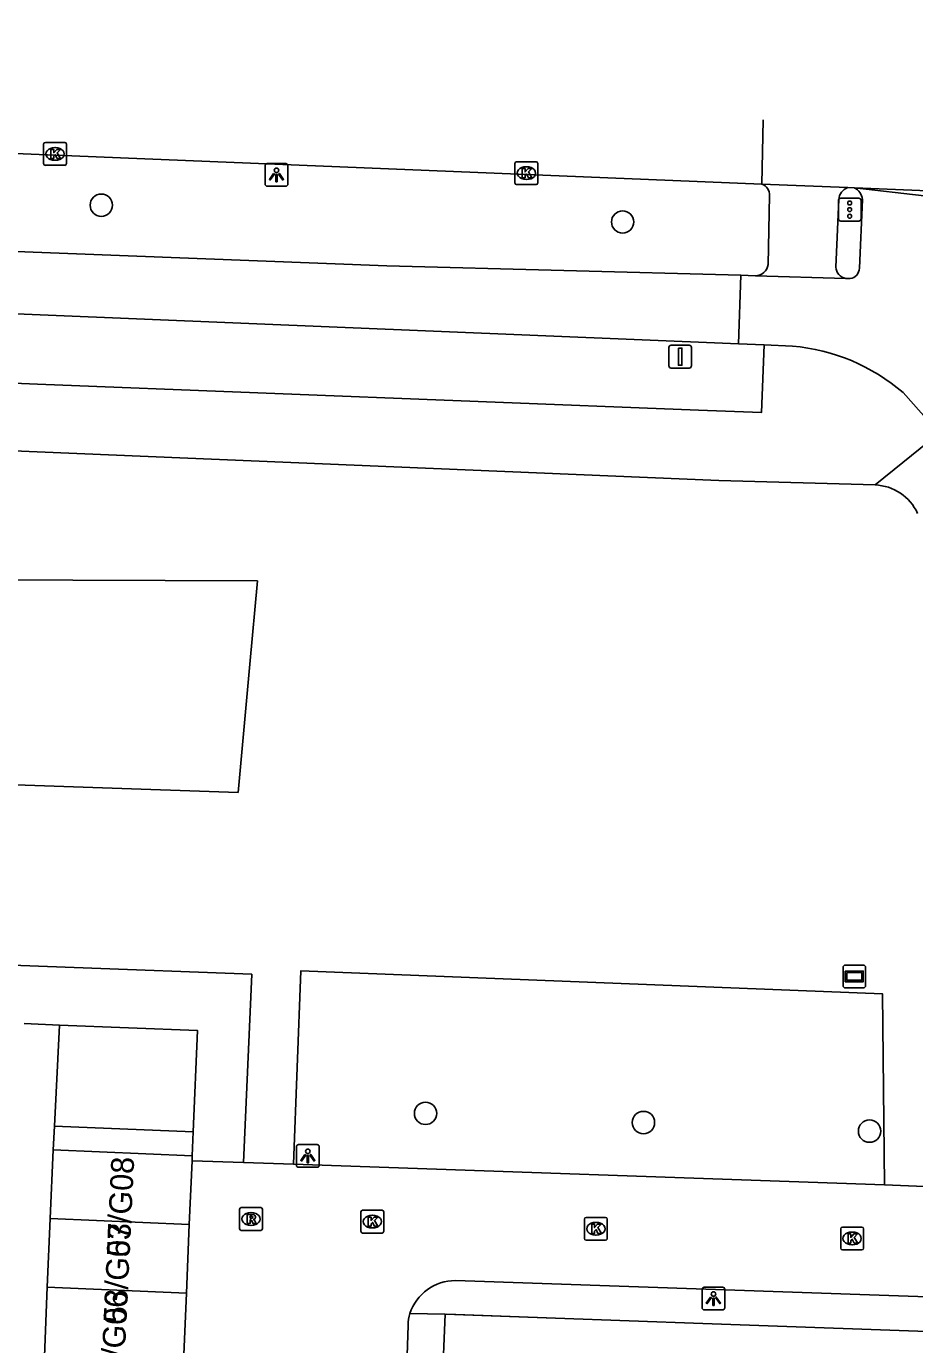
# Model space of a CAD drawing. Extents: x 161355 to 162026, y 386504 to 387459.
# Drawn here: x 161707.5 to 161746.4, y 387393.1 to 387450.8 of the extents above; entities that cross this region are included whole.
import ezdxf

# ---------------------------------------------------------------- set-up
doc = ezdxf.new("R2010")
doc.units = 0
for name, color, linetype in [('IMGEO_Boom', 7, 'Continuous'), ('IMGEO_Fietspad_gesloten', 7, 'Continuous'), ('IMGEO_Fietspad_open', 7, 'Continuous'), ('IMGEO_Groenvoorziening', 7, 'Continuous'), ('IMGEO_Kolk', 7, 'Continuous'), ('IMGEO_Lichtpunt', 7, 'Continuous'), ('IMGEO_Muur', 7, 'Continuous'), ('IMGEO_Pand', 7, 'Continuous'), ('IMGEO_Pand_nummerreeks', 7, 'Continuous'), ('IMGEO_Rijbaan_lokaal_gesloten', 7, 'Continuous'), ('IMGEO_Rijbaan_lokaal_open', 7, 'Continuous'), ('IMGEO_Rioolput', 7, 'Continuous'), ('IMGEO_Verkeersbordpaal', 7, 'Continuous'), ('IMGEO_Verkeersregelinstallatiepaal', 7, 'Continuous'), ('IMGEO_Verklikker', 7, 'Continuous'), ('IMGEO_Voetpad_open', 7, 'Continuous')]:
    doc.layers.add(name, color=color, linetype=linetype)

msp = doc.modelspace()

# ---------------------------------------------------------------- linework, layer by layer
at = {"layer": 'IMGEO_Boom'}
for centre in [(161710.741, 387443.016), (161733.577, 387442.282), (161724.944, 387403.261), (161734.491, 387402.86), (161744.394, 387402.483)]:
    msp.add_circle(centre, 0.489, dxfattribs=at)
at = {"layer": 'IMGEO_Fietspad_gesloten'}
for points in [[(161612.89, 387444.91), (161652.822, 387443.267), (161706.244, 387441.015), (161723.243, 387440.365), (161738.753, 387439.947)], [(161610.883, 387442.256), (161612.683, 387442.214), (161614.558, 387442.129), (161644.429, 387440.874), (161676.294, 387439.535), (161679.83, 387439.386), (161708.067, 387438.213), (161738.649, 387436.943)], [(161738.753, 387439.947), (161738.649, 387436.943)]]:
    msp.add_lwpolyline(points, dxfattribs=at)
at = {"layer": 'IMGEO_Fietspad_open'}
for points in [[(161744.081, 387443.272), (161743.952, 387440.258)], [(161739.398, 387439.93), (161738.753, 387439.947)], [(161743.359, 387439.812), (161739.398, 387439.93)], [(161743.542, 387439.801), (161743.359, 387439.812)], [(161738.649, 387436.943), (161739.77, 387436.897)], [(161739.77, 387436.897), (161741.023, 387436.845)], [(161745.866, 387434.812), (161747.439, 387433.041)]]:
    msp.add_lwpolyline(points, dxfattribs=at)
for centre, radius, start, end in [((161743.477, 387443.221), 0.606, 4.7809, 64.80063), ((161743.474, 387440.274), 0.478, 278.16907, 358.03686), ((161740.308, 387428.357), 8.518, 49.27042, 85.18609)]:
    msp.add_arc(centre, radius, start, end, dxfattribs=at)
at = {"layer": 'IMGEO_Groenvoorziening'}
for points in [[(161697.286, 387423.717), (161697.204, 387417.981), (161716.731, 387417.308), (161717.248, 387422.919), (161717.584, 387426.568), (161697.328, 387426.639), (161697.286, 387423.717)], [(161745.049, 387400.136), (161744.963, 387408.488), (161719.485, 387409.508), (161719.159, 387401.034)]]:
    msp.add_lwpolyline(points, dxfattribs=at)
at = {"layer": 'IMGEO_Kolk'}
for p, q in [((161708.216, 387444.836), (161708.216, 387445.688)), ((161708.291, 387445.762), (161709.143, 387445.762)), ((161708.704, 387445.542), (161708.729, 387445.542)), ((161709.217, 387445.688), (161709.217, 387444.836)), ((161708.727, 387444.982), (161708.702, 387444.982)), ((161728.861, 387443.995), (161728.861, 387444.847)), ((161728.936, 387444.921), (161729.788, 387444.921)), ((161729.862, 387444.847), (161729.862, 387443.995)), ((161709.143, 387444.762), (161708.291, 387444.762)), ((161729.349, 387444.701), (161729.374, 387444.701)), ((161729.788, 387443.921), (161728.936, 387443.921)), ((161729.372, 387444.141), (161729.347, 387444.141)), ((161722.115, 387398.098), (161722.115, 387398.95)), ((161722.19, 387399.024), (161723.042, 387399.024)), ((161722.603, 387398.804), (161722.628, 387398.804)), ((161723.116, 387398.95), (161723.116, 387398.098)), ((161731.905, 387397.784), (161731.905, 387398.636)), ((161731.98, 387398.71), (161732.832, 387398.71)), ((161732.906, 387398.636), (161732.906, 387397.784)), ((161722.626, 387398.244), (161722.601, 387398.244)), ((161732.393, 387398.49), (161732.418, 387398.49)), ((161743.129, 387397.36), (161743.129, 387398.212)), ((161743.204, 387398.286), (161744.056, 387398.286)), ((161743.617, 387398.066), (161743.642, 387398.066)), ((161744.13, 387398.212), (161744.13, 387397.36)), ((161723.042, 387398.024), (161722.19, 387398.024)), ((161732.832, 387397.71), (161731.98, 387397.71)), ((161732.416, 387397.93), (161732.391, 387397.93)), ((161743.64, 387397.506), (161743.615, 387397.506)), ((161744.056, 387397.286), (161743.204, 387397.286))]:
    msp.add_line(p, q, dxfattribs=at)
for points in [[(161708.216, 387444.836), (161708.216, 387445.688)], [(161708.291, 387445.762), (161709.143, 387445.762)], [(161708.537, 387445.462), (161708.66, 387445.462), (161708.66, 387445.311), (161708.79, 387445.462), (161708.954, 387445.462), (161708.808, 387445.311), (161708.961, 387445.062), (161708.809, 387445.062), (161708.724, 387445.226), (161708.66, 387445.159), (161708.66, 387445.062), (161708.537, 387445.062), (161708.537, 387445.462)], [(161709.217, 387445.688), (161709.217, 387444.836)], [(161728.861, 387443.995), (161728.861, 387444.847)], [(161728.936, 387444.921), (161729.788, 387444.921)], [(161729.862, 387444.847), (161729.862, 387443.995)], [(161709.143, 387444.762), (161708.291, 387444.762)], [(161729.182, 387444.621), (161729.305, 387444.621), (161729.305, 387444.47), (161729.435, 387444.621), (161729.599, 387444.621), (161729.453, 387444.47), (161729.606, 387444.221), (161729.454, 387444.221), (161729.369, 387444.385), (161729.305, 387444.318), (161729.305, 387444.221), (161729.182, 387444.221), (161729.182, 387444.621)], [(161729.788, 387443.921), (161728.936, 387443.921)], [(161722.115, 387398.098), (161722.115, 387398.95)], [(161722.19, 387399.024), (161723.042, 387399.024)], [(161722.436, 387398.724), (161722.559, 387398.724), (161722.559, 387398.573), (161722.689, 387398.724), (161722.853, 387398.724), (161722.707, 387398.573), (161722.86, 387398.324), (161722.708, 387398.324), (161722.623, 387398.488), (161722.559, 387398.421), (161722.559, 387398.324), (161722.436, 387398.324), (161722.436, 387398.724)], [(161723.116, 387398.95), (161723.116, 387398.098)], [(161731.905, 387397.784), (161731.905, 387398.636)], [(161731.98, 387398.71), (161732.832, 387398.71)], [(161732.906, 387398.636), (161732.906, 387397.784)], [(161732.226, 387398.41), (161732.349, 387398.41), (161732.349, 387398.259), (161732.479, 387398.41), (161732.643, 387398.41), (161732.497, 387398.259), (161732.65, 387398.01), (161732.498, 387398.01), (161732.413, 387398.174), (161732.349, 387398.107), (161732.349, 387398.01), (161732.226, 387398.01), (161732.226, 387398.41)], [(161743.129, 387397.36), (161743.129, 387398.212)], [(161743.204, 387398.286), (161744.056, 387398.286)], [(161744.13, 387398.212), (161744.13, 387397.36)], [(161723.042, 387398.024), (161722.19, 387398.024)], [(161732.832, 387397.71), (161731.98, 387397.71)], [(161743.45, 387397.986), (161743.573, 387397.986), (161743.573, 387397.835), (161743.703, 387397.986), (161743.867, 387397.986), (161743.721, 387397.835), (161743.874, 387397.586), (161743.722, 387397.586), (161743.637, 387397.75), (161743.573, 387397.683), (161743.573, 387397.586), (161743.45, 387397.586), (161743.45, 387397.986)], [(161744.056, 387397.286), (161743.204, 387397.286)]]:
    msp.add_lwpolyline(points, dxfattribs=at)
for centre, start, end in [((161708.293, 387445.686), 91.55205, 178.44795), ((161708.293, 387445.686), 91.55205, 178.44795), ((161709.141, 387445.686), 1.55205, 88.44795), ((161709.141, 387445.686), 1.55205, 88.44795), ((161708.293, 387444.838), 181.55205, 268.44795), ((161708.293, 387444.838), 181.55205, 268.44795), ((161709.141, 387444.838), 271.55205, 358.44795), ((161709.141, 387444.838), 271.55205, 358.44795), ((161728.938, 387444.845), 91.55205, 178.44795), ((161728.938, 387444.845), 91.55205, 178.44795), ((161729.786, 387444.845), 1.55205, 88.44795), ((161729.786, 387444.845), 1.55205, 88.44795), ((161728.938, 387443.997), 181.55205, 268.44795), ((161728.938, 387443.997), 181.55205, 268.44795), ((161729.786, 387443.997), 271.55205, 358.44795), ((161729.786, 387443.997), 271.55205, 358.44795), ((161722.192, 387398.948), 91.55205, 178.44795), ((161722.192, 387398.948), 91.55205, 178.44795), ((161723.04, 387398.948), 1.55205, 88.44795), ((161723.04, 387398.948), 1.55205, 88.44795), ((161731.982, 387398.634), 91.55205, 178.44795), ((161731.982, 387398.634), 91.55205, 178.44795), ((161732.83, 387398.634), 1.55205, 88.44795), ((161732.83, 387398.634), 1.55205, 88.44795), ((161722.192, 387398.1), 181.55205, 268.44795), ((161722.192, 387398.1), 181.55205, 268.44795), ((161723.04, 387398.1), 271.55205, 358.44795), ((161723.04, 387398.1), 271.55205, 358.44795), ((161743.206, 387398.21), 91.55205, 178.44795), ((161743.206, 387398.21), 91.55205, 178.44795), ((161744.054, 387398.21), 1.55205, 88.44795), ((161744.054, 387398.21), 1.55205, 88.44795), ((161731.982, 387397.786), 181.55205, 268.44795), ((161731.982, 387397.786), 181.55205, 268.44795), ((161732.83, 387397.786), 271.55205, 358.44795), ((161732.83, 387397.786), 271.55205, 358.44795), ((161743.206, 387397.362), 181.55205, 268.44795), ((161743.206, 387397.362), 181.55205, 268.44795), ((161744.054, 387397.362), 271.55205, 358.44795), ((161744.054, 387397.362), 271.55205, 358.44795)]:
    msp.add_arc(centre, 0.0765, start, end, dxfattribs=at)
for centre, major_axis, ratio, start_param, end_param in [((161708.703, 387445.262), (-0.387, 0.002), 0.722429, 4.712389, 7.853982), ((161708.728, 387445.262), (-0.39, 0.002), 0.717154, 1.570796, 4.712389), ((161729.348, 387444.421), (-0.387, 0.002), 0.722429, 4.712389, 7.853982), ((161729.373, 387444.421), (-0.39, 0.002), 0.717154, 1.570796, 4.712389), ((161722.602, 387398.524), (-0.387, 0.002), 0.722429, 4.712389, 7.853982), ((161722.627, 387398.524), (-0.39, 0.002), 0.717154, 1.570796, 4.712389), ((161732.392, 387398.21), (-0.387, 0.002), 0.722429, 4.712389, 7.853982), ((161732.417, 387398.21), (-0.39, 0.002), 0.717154, 1.570796, 4.712389), ((161743.616, 387397.786), (-0.387, 0.002), 0.722429, 4.712389, 7.853982), ((161743.641, 387397.786), (-0.39, 0.002), 0.717154, 1.570796, 4.712389)]:
    msp.add_ellipse(centre, major_axis=major_axis, ratio=ratio, start_param=start_param, end_param=end_param, dxfattribs=at)
at = {"layer": 'IMGEO_Lichtpunt'}
for p, q in [((161718.819, 387444.841), (161718.011, 387444.841)), ((161718.819, 387444.841), (161718.011, 387444.841)), ((161717.917, 387444.746), (161717.917, 387443.939)), ((161717.917, 387444.746), (161717.917, 387443.939)), ((161718.913, 387443.939), (161718.913, 387444.746)), ((161718.913, 387443.939), (161718.913, 387444.746)), ((161718.011, 387443.845), (161718.819, 387443.845)), ((161718.011, 387443.845), (161718.819, 387443.845)), ((161719.289, 387401.801), (161719.289, 387400.994)), ((161719.289, 387401.801), (161719.289, 387400.994)), ((161720.191, 387401.896), (161719.383, 387401.896)), ((161720.191, 387401.896), (161719.383, 387401.896)), ((161720.285, 387400.994), (161720.285, 387401.801)), ((161720.285, 387400.994), (161720.285, 387401.801)), ((161719.383, 387400.9), (161720.191, 387400.9)), ((161719.383, 387400.9), (161720.191, 387400.9)), ((161737.057, 387395.559), (161737.057, 387394.752)), ((161737.057, 387395.559), (161737.057, 387394.752)), ((161737.959, 387395.654), (161737.151, 387395.654)), ((161737.959, 387395.654), (161737.151, 387395.654)), ((161738.053, 387394.752), (161738.053, 387395.559)), ((161738.053, 387394.752), (161738.053, 387395.559)), ((161737.151, 387394.658), (161737.959, 387394.658)), ((161737.151, 387394.658), (161737.959, 387394.658))]:
    msp.add_line(p, q, dxfattribs=at)
for points in [[(161718.291, 387444.41), (161718.33, 387444.382), (161718.142, 387444.12), (161718.104, 387444.147), (161718.291, 387444.41)], [(161718.393, 387444.362), (161718.44, 387444.362), (161718.44, 387444.04), (161718.393, 387444.04), (161718.393, 387444.362)], [(161718.503, 387444.382), (161718.541, 387444.409), (161718.728, 387444.147), (161718.689, 387444.119), (161718.503, 387444.382)], [(161719.663, 387401.465), (161719.702, 387401.437), (161719.514, 387401.175), (161719.476, 387401.202), (161719.663, 387401.465)], [(161719.765, 387401.417), (161719.812, 387401.417), (161719.812, 387401.095), (161719.765, 387401.095), (161719.765, 387401.417)], [(161719.875, 387401.437), (161719.913, 387401.464), (161720.1, 387401.202), (161720.061, 387401.174), (161719.875, 387401.437)], [(161737.431, 387395.223), (161737.47, 387395.195), (161737.282, 387394.933), (161737.244, 387394.96), (161737.431, 387395.223)], [(161737.533, 387395.175), (161737.58, 387395.175), (161737.58, 387394.853), (161737.533, 387394.853), (161737.533, 387395.175)], [(161737.643, 387395.195), (161737.681, 387395.222), (161737.868, 387394.96), (161737.829, 387394.932), (161737.643, 387395.195)]]:
    msp.add_lwpolyline(points, dxfattribs=at)
for centre in [(161718.416, 387444.544), (161719.788, 387401.599), (161737.556, 387395.357)]:
    msp.add_circle(centre, 0.0994, dxfattribs=at)
for centre, start, end in [((161718.011, 387444.746), 90, 180), ((161718.011, 387444.746), 90, 180), ((161718.819, 387444.746), 0, 90), ((161718.819, 387444.746), 0, 90), ((161718.011, 387443.939), 180, 270), ((161718.011, 387443.939), 180, 270), ((161718.819, 387443.939), 270, 0), ((161718.819, 387443.939), 270, 360), ((161719.383, 387401.801), 90, 180), ((161719.383, 387401.801), 90, 180), ((161720.191, 387401.801), 0, 90), ((161720.191, 387401.801), 0, 90), ((161719.383, 387400.994), 180, 270), ((161719.383, 387400.994), 180, 270), ((161720.191, 387400.994), 270, 0), ((161720.191, 387400.994), 270, 360), ((161737.151, 387395.559), 90, 180), ((161737.151, 387395.559), 90, 180), ((161737.959, 387395.559), 0, 90), ((161737.959, 387395.559), 0, 90), ((161737.151, 387394.752), 180, 270), ((161737.151, 387394.752), 180, 270), ((161737.959, 387394.752), 270, 0), ((161737.959, 387394.752), 270, 360)]:
    msp.add_arc(centre, 0.0946, start, end, dxfattribs=at)
at = {"layer": 'IMGEO_Muur'}
for points in [[(161730.634, 387394.295), (161725.877, 387394.465)], [(161737.09, 387394.064), (161730.634, 387394.295)]]:
    msp.add_lwpolyline(points, dxfattribs=at)
at = {"layer": 'IMGEO_Pand'}
for points in [[(161708.504, 387398.659), (161708.633, 387401.67)], [(161708.633, 387401.67), (161714.727, 387401.41)], [(161714.717, 387401.188), (161714.598, 387398.399)], [(161714.727, 387401.41), (161714.717, 387401.188)], [(161708.504, 387398.659), (161708.375, 387395.648)], [(161714.598, 387398.399), (161708.504, 387398.659)], [(161714.469, 387395.388), (161714.598, 387398.399)], [(161708.375, 387395.648), (161708.247, 387392.637)], [(161708.375, 387395.648), (161714.469, 387395.388)], [(161714.341, 387392.376), (161714.469, 387395.388)]]:
    msp.add_lwpolyline(points, dxfattribs=at)
at = {"layer": 'IMGEO_Rijbaan_lokaal_gesloten'}
for points in [[(161566.731, 387450.192), (161568.939, 387450.72), (161570.123, 387450.845), (161577.085, 387450.606), (161735.771, 387444.103), (161739.669, 387443.941)], [(161739.727, 387446.755), (161739.669, 387443.941)], [(161739.669, 387443.941), (161743.437, 387443.79)], [(161743.437, 387443.79), (161743.735, 387443.77)], [(161743.735, 387443.77), (161776.351, 387442.45)], [(161747.604, 387443.2), (161746.786, 387443.427), (161743.735, 387443.77)]]:
    msp.add_lwpolyline(points, dxfattribs=at)
at = {"layer": 'IMGEO_Rijbaan_lokaal_open'}
for points in [[(161714.717, 387401.188), (161716.965, 387401.11)], [(161719.159, 387401.034), (161716.965, 387401.11)], [(161719.159, 387401.034), (161745.049, 387400.136)], [(161749.25, 387399.959), (161745.049, 387400.136)], [(161749.03, 387395.163), (161726.254, 387395.942)], [(161724.178, 387393.997), (161724.083, 387390.891)]]:
    msp.add_lwpolyline(points, dxfattribs=at)
for centre, radius, start, end in [((161726.254, 387393.839), 2.103, 90.00254, 161.6518), ((161725.723, 387394.01), 1.545, 161.47669, 180.48467)]:
    msp.add_arc(centre, radius, start, end, dxfattribs=at)
at = {"layer": 'IMGEO_Rioolput'}
for p, q in [((161716.8, 387398.211), (161716.8, 387399.063)), ((161716.875, 387399.137), (161717.727, 387399.137)), ((161717.288, 387398.917), (161717.313, 387398.917)), ((161717.801, 387399.063), (161717.801, 387398.211)), ((161717.727, 387398.137), (161716.875, 387398.137)), ((161717.311, 387398.357), (161717.286, 387398.357))]:
    msp.add_line(p, q, dxfattribs=at)
for points in [[(161716.8, 387398.211), (161716.8, 387399.063)], [(161716.875, 387399.137), (161717.727, 387399.137)], [(161717.389, 387398.835), (161717.137, 387398.837), (161717.137, 387398.437)], [(161717.315, 387398.756), (161717.261, 387398.756), (161717.261, 387398.675)], [(161717.261, 387398.675), (161717.313, 387398.675)], [(161717.801, 387399.063), (161717.801, 387398.211)], [(161717.727, 387398.137), (161716.875, 387398.137)], [(161717.137, 387398.437), (161717.261, 387398.437), (161717.261, 387398.599), (161717.272, 387398.599)], [(161717.319, 387398.57), (161717.39, 387398.437), (161717.53, 387398.437), (161717.465, 387398.563)]]:
    msp.add_lwpolyline(points, dxfattribs=at)
for centre, radius, start, end in [((161716.877, 387399.061), 0.0765, 91.55205, 178.44795), ((161716.877, 387399.061), 0.0765, 91.55205, 178.44795), ((161717.297, 387398.864), 0.19, 274.7715, 282.96867), ((161717.321, 387398.66), 0.0964, 77.00612, 93.18647), ((161717.335, 387398.717), 0.0378, 276.66336, 79.67722), ((161717.388, 387398.725), 0.109, 350.36119, 89.41601), ((161717.386, 387398.725), 0.112, 277.58423, 350.98172), ((161717.725, 387399.061), 0.0765, 1.55205, 88.44795), ((161717.725, 387399.061), 0.0765, 1.55205, 88.44795), ((161716.877, 387398.213), 0.0765, 181.55205, 268.44795), ((161716.877, 387398.213), 0.0765, 181.55205, 268.44795), ((161717.271, 387398.546), 0.0533, 26.02933, 88.69889), ((161717.37, 387398.51), 0.108, 29.51342, 73.79051), ((161717.725, 387398.213), 0.0765, 271.55205, 358.44795), ((161717.725, 387398.213), 0.0765, 271.55205, 358.44795)]:
    msp.add_arc(centre, radius, start, end, dxfattribs=at)
for centre, major_axis, ratio, start_param, end_param in [((161717.287, 387398.637), (-0.387, 0.002), 0.722429, 4.712389, 7.853982), ((161717.312, 387398.637), (-0.39, 0.002), 0.717154, 1.570796, 4.712389)]:
    msp.add_ellipse(centre, major_axis=major_axis, ratio=ratio, start_param=start_param, end_param=end_param, dxfattribs=at)
at = {"layer": 'IMGEO_Verkeersbordpaal'}
for p, q in [((161735.603, 387435.989), (161735.603, 387436.789)), ((161735.603, 387436.789), (161735.603, 387435.989)), ((161735.703, 387436.889), (161736.493, 387436.889)), ((161736.493, 387436.889), (161735.703, 387436.889)), ((161736.593, 387436.789), (161736.593, 387435.989)), ((161736.593, 387435.989), (161736.593, 387436.789)), ((161736.493, 387435.889), (161735.703, 387435.889)), ((161735.703, 387435.889), (161736.493, 387435.889))]:
    msp.add_line(p, q, dxfattribs=at)
msp.add_lwpolyline([(161736.023, 387436.764), (161736.173, 387436.764), (161736.173, 387436.014), (161736.023, 387436.014), (161736.023, 387436.764)], dxfattribs=at)
for centre, start, end in [((161735.703, 387436.789), 90, 180), ((161735.703, 387436.789), 90, 180), ((161736.493, 387436.789), 0, 90), ((161736.493, 387436.789), 360, 90), ((161735.703, 387435.989), 180, 270), ((161735.703, 387435.989), 180, 270), ((161736.493, 387435.989), 270, 0), ((161736.493, 387435.989), 270, 0)]:
    msp.add_arc(centre, 0.1, start, end, dxfattribs=at)
at = {"layer": 'IMGEO_Verkeersregelinstallatiepaal'}
for p, q in [((161743.029, 387442.423), (161743.029, 387443.223)), ((161743.029, 387443.223), (161743.029, 387442.423)), ((161743.129, 387443.323), (161743.919, 387443.323)), ((161743.919, 387443.323), (161743.129, 387443.323)), ((161744.019, 387443.223), (161744.019, 387442.423)), ((161744.019, 387442.423), (161744.019, 387443.223)), ((161743.919, 387442.323), (161743.129, 387442.323)), ((161743.129, 387442.323), (161743.919, 387442.323))]:
    msp.add_line(p, q, dxfattribs=at)
for centre in [(161743.524, 387443.113), (161743.524, 387442.823), (161743.524, 387442.533)]:
    msp.add_circle(centre, 0.085, dxfattribs=at)
for centre, start, end in [((161743.129, 387443.223), 90, 180), ((161743.129, 387443.223), 90, 180), ((161743.919, 387443.223), 0, 90), ((161743.919, 387443.223), 360, 90), ((161743.129, 387442.423), 180, 270), ((161743.129, 387442.423), 180, 270), ((161743.919, 387442.423), 270, 0), ((161743.919, 387442.423), 270, 0)]:
    msp.add_arc(centre, 0.1, start, end, dxfattribs=at)
at = {"layer": 'IMGEO_Verklikker'}
for p, q in [((161743.231, 387408.856), (161743.231, 387409.656)), ((161743.231, 387409.656), (161743.231, 387408.856)), ((161743.331, 387409.756), (161744.121, 387409.756)), ((161744.121, 387409.756), (161743.331, 387409.756)), ((161744.221, 387409.656), (161744.221, 387408.856)), ((161744.221, 387408.856), (161744.221, 387409.656)), ((161744.121, 387408.756), (161743.331, 387408.756)), ((161743.331, 387408.756), (161744.121, 387408.756))]:
    msp.add_line(p, q, dxfattribs=at)
for points in [[(161743.332, 387409.488), (161744.12, 387409.488), (161744.12, 387409.024), (161743.332, 387409.024), (161743.332, 387409.488)], [(161743.397, 387409.423), (161743.397, 387409.089), (161744.055, 387409.089), (161744.055, 387409.423), (161743.397, 387409.423)]]:
    msp.add_lwpolyline(points, dxfattribs=at)
for centre, start, end in [((161743.331, 387409.656), 90, 180), ((161743.331, 387409.656), 90, 180), ((161744.121, 387409.656), 0, 90), ((161744.121, 387409.656), 360, 90), ((161743.331, 387408.856), 180, 270), ((161743.331, 387408.856), 180, 270), ((161744.121, 387408.856), 270, 0), ((161744.121, 387408.856), 270, 0)]:
    msp.add_arc(centre, 0.1, start, end, dxfattribs=at)
at = {"layer": 'IMGEO_Voetpad_open'}
for points in [[(161739.947, 387440.422), (161740.016, 387443.436)], [(161743.048, 387443.264), (161742.918, 387440.305)], [(161739.77, 387436.897), (161739.654, 387433.94), (161736.908, 387434.048), (161707.941, 387435.177), (161676.122, 387436.495), (161644.302, 387437.813), (161628.393, 387438.471)], [(161657.925, 387434.327), (161737.785, 387430.965), (161744.638, 387430.769)], [(161744.638, 387430.769), (161747.439, 387433.041)], [(161716.965, 387401.11), (161717.333, 387409.351), (161655.059, 387411.688)], [(161707.367, 387407.191), (161708.915, 387407.129)], [(161708.686, 387402.702), (161708.915, 387407.129)], [(161708.915, 387407.129), (161714.96, 387406.886), (161714.772, 387402.456)], [(161708.686, 387402.702), (161708.633, 387401.67)], [(161714.772, 387402.456), (161708.686, 387402.702)], [(161714.772, 387402.456), (161714.727, 387401.41)], [(161724.258, 387394.501), (161725.808, 387394.467)], [(161725.68, 387391.296), (161725.808, 387394.467)], [(161725.808, 387394.467), (161730.634, 387394.295), (161737.09, 387394.064), (161748.96, 387393.639)]]:
    msp.add_lwpolyline(points, dxfattribs=at)
for centre, radius, start, end in [((161739.521, 387443.468), 0.496, 356.3258, 72.66235), ((161743.631, 387443.24), 0.583, 109.38956, 177.64135), ((161739.395, 387440.486), 0.556, 270.30371, 353.42808), ((161743.434, 387440.323), 0.517, 182.01741, 261.60934), ((161744.565, 387428.647), 2.123, 24.50946, 88.03931)]:
    msp.add_arc(centre, radius, start, end, dxfattribs=at)

# ---------------------------------------------------------------- texts
at = {"layer": 'IMGEO_Pand_nummerreeks'}
for s, rotation, p in [('53/G08', 87.30158, (161711.98, 387396.955)), ('53/G07', 87.30119, (161711.839, 387394.057)), ('53/G06', 87.30119, (161711.697, 387391.092))]:
    msp.add_text(s, height=1, rotation=rotation, dxfattribs=at).set_placement(p)

doc.saveas('drawing.dxf')
